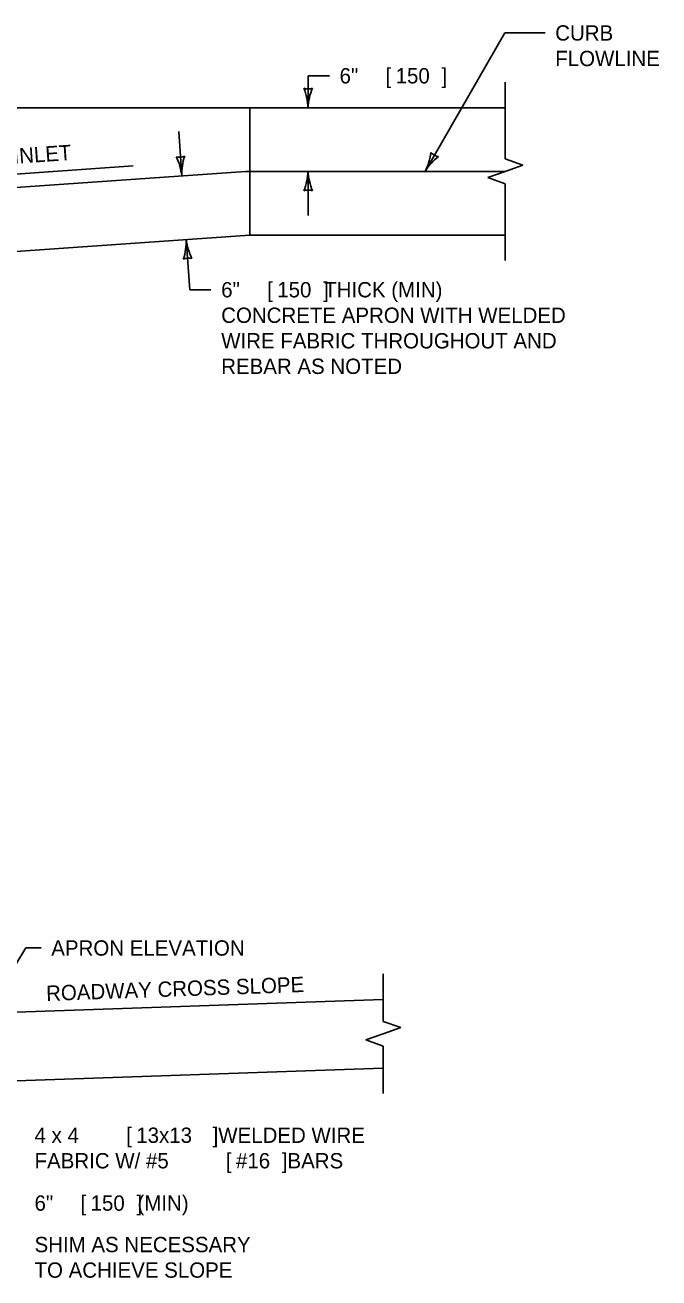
# Model space of a CAD drawing. Extents: x 49991.4 to 50048.3, y 49987.6 to 50018.3.
# Drawn here: x 50044.738 to 50047.223, y 49999.431 to 50004.338 of the extents above; entities that cross this region are included whole.
import ezdxf

# ---------------------------------------------------------------- set-up
doc = ezdxf.new("R2010")
doc.units = 0
for name, color, linetype in [('Level 1', 7, 'Continuous'), ('Level 2', 7, 'Continuous'), ('Level 3', 7, 'Continuous'), ('Level 6', 7, 'Continuous')]:
    doc.layers.add(name, color=color, linetype=linetype)

msp = doc.modelspace()

# ---------------------------------------------------------------- linework, layer by layer
at = {"layer": 'Level 1'}
for p, q in [((50046.6203, 50004.0142), (50040.5028, 50004.0142)), ((50045.619, 50004.0142), (50045.619, 50003.5154)), ((50045.6016, 50003.7648), (50044.1053, 50003.6602)), ((50045.6016, 50003.7648), (50045.619, 50003.7648)), ((50046.6203, 50003.7648), (50045.619, 50003.7648)), ((50044.2726, 50003.4213), (50045.619, 50003.5154)), ((50045.619, 50003.5154), (50046.6203, 50003.5154)), ((50044.5853, 50000.467), (50046.142, 50000.5214)), ((50044.5853, 50000.1982), (50046.142, 50000.2526))]:
    msp.add_line(p, q, dxfattribs=at)
at = {"layer": 'Level 3'}
for p, q in [((50046.3058, 50003.7648), (50046.6187, 50004.3069)), ((50046.6187, 50004.3069), (50046.776, 50004.3069)), ((50045.8474, 50004.0142), (50045.8474, 50004.1392)), ((50045.8474, 50004.1392), (50045.9307, 50004.1392)), ((50045.3401, 50003.9204), (50045.3522, 50003.7474)), ((50045.162, 50003.7863), (50044.1016, 50003.7122)), ((50045.8474, 50003.7648), (50045.8474, 50003.5914)), ((50045.3696, 50003.498), (50045.3834, 50003.3012)), ((50045.3834, 50003.3012), (50045.4667, 50003.3012)), ((50044.7406, 50000.7229), (50044.5853, 50000.467)), ((50044.8006, 50000.7229), (50044.7406, 50000.7229))]:
    msp.add_line(p, q, dxfattribs=at)
for centre, radius, start, end in [((50045.8474, 50004.1424), 0.0548, 252.1388, 287.8612), ((50045.6146, 50004.0027), 0.233, 2.8273, 22.0772), ((50046.0695, 50004.0051), 0.2223, 157.456, 177.6395), ((50045.3433, 50003.8753), 0.0548, 256.1388, 291.8612), ((50045.1209, 50003.7197), 0.233, 6.8273, 26.0772), ((50045.5744, 50003.7538), 0.2223, 161.456, 181.6395), ((50046.0985, 50003.8712), 0.233, 332.8273, 352.0772), ((50046.4936, 50003.6458), 0.2223, 127.456, 147.6395), ((50046.3699, 50003.8759), 0.0548, 222.1388, 257.8612), ((50045.6252, 50003.774), 0.2223, 337.456, 357.6395), ((50046.0801, 50003.7763), 0.233, 182.8273, 202.0772), ((50045.8474, 50003.6366), 0.0548, 72.1388, 107.8612), ((50045.1474, 50003.4916), 0.2223, 341.456, 1.6395), ((50045.601, 50003.5257), 0.233, 186.8273, 206.0772), ((50045.3786, 50003.3701), 0.0548, 76.1388, 111.8612)]:
    msp.add_arc(centre, radius, start, end, dxfattribs=at)
at = {"layer": 'Level 6'}
for p, q in [((50046.6203, 50004.1142), (50046.6203, 50003.8134)), ((50046.6889, 50003.7891), (50046.6203, 50003.8134)), ((50046.6203, 50003.7648), (50046.5517, 50003.7405)), ((50046.6889, 50003.7891), (50046.6203, 50003.7648)), ((50046.6203, 50003.7162), (50046.5517, 50003.7405)), ((50046.6203, 50003.7162), (50046.6203, 50003.4154)), ((50046.142, 50000.6214), (50046.142, 50000.4356)), ((50046.2106, 50000.4113), (50046.142, 50000.4356)), ((50046.2106, 50000.4113), (50046.142, 50000.387)), ((50046.142, 50000.387), (50046.0734, 50000.3627)), ((50046.142, 50000.3384), (50046.0734, 50000.3627)), ((50046.142, 50000.3384), (50046.142, 50000.1526))]:
    msp.add_line(p, q, dxfattribs=at)

# ---------------------------------------------------------------- texts
at = {"layer": 'Level 2'}
for s, p in [('CURB', (50046.816, 50004.2769)), ('FLOWLINE', (50046.816, 50004.1769)), ('6" ', (50045.9707, 50004.1092)), ('[', (50046.1507, 50004.1092)), ('150', (50046.1904, 50004.1092)), (']', (50046.3704, 50004.1092)), ('6" ', (50045.5067, 50003.2712)), ('[', (50045.6867, 50003.2712)), ('150', (50045.7264, 50003.2712)), (']', (50045.9064, 50003.2712)), ('  THICK (MIN) ', (50045.8658, 50003.2712)), ('CONCRETE APRON WITH WELDED ', (50045.5067, 50003.1712)), ('WIRE FABRIC THROUGHOUT AND ', (50045.5067, 50003.0712)), ('REBAR AS NOTED', (50045.5067, 50002.9712)), ('APRON ELEVATION', (50044.8406, 50000.6929)), ('4 x 4 ', (50044.775, 49999.9596)), ('[', (50045.134, 49999.9596)), ('13x13', (50045.1737, 49999.9596)), (']', (50045.4732, 49999.9596)), (' WELDED WIRE', (50045.4728, 49999.9596)), ('FABRIC W/ #5 ', (50044.775, 49999.8596)), ('[', (50045.525, 49999.8596)), ('#16', (50045.5647, 49999.8596)), (']', (50045.7447, 49999.8596)), (' BARS', (50045.7442, 49999.8596)), ('6" ', (50044.775, 49999.6938)), ('[', (50044.955, 49999.6938)), ('150', (50044.9947, 49999.6938)), (']', (50045.1747, 49999.6938)), ('  (MIN)', (50045.134, 49999.6938)), ('SHIM AS NECESSARY', (50044.775, 49999.5314)), ('TO ACHIEVE SLOPE', (50044.775, 49999.4314))]:
    msp.add_text(s, height=0.06, dxfattribs=at).set_placement(p)
for s, rotation, p in [('SLOPE TO INLET', 4, (50044.272, 50003.7642)), ('ROADWAY CROSS SLOPE', 2, (50044.8214, 50000.5153))]:
    msp.add_text(s, height=0.06, rotation=rotation, dxfattribs=at).set_placement(p)

doc.saveas('drawing.dxf')
